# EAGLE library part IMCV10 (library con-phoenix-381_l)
Invertierter Mini-Combicon 3.81mm vertikal 10-polig IMCV 1,5/10-G-3,81 (ohne Gegenstecker)
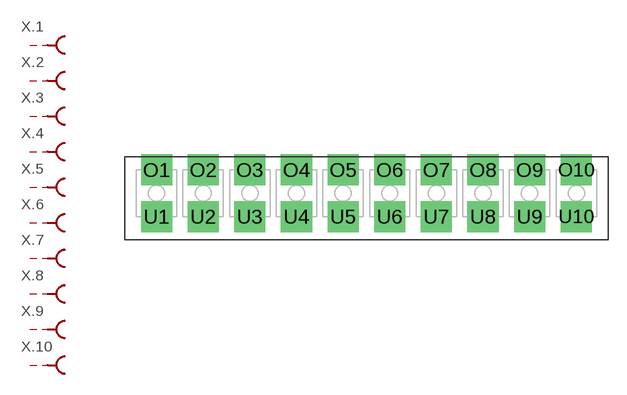
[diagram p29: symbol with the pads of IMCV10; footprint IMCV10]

Designator prefix X; gates .5=MCBU .4=MCBU .3=MCBU .2=MCBU .1=MCBU .6=MCBU .7=MCBU .8=MCBU .9=MCBU .10=MCBU

## IMCV10  [IMCV10]
O1  .1:S  pas
O2  .2:S  pas
O3  .3:S  pas
O4  .4:S  pas
O5  .5:S  pas
O6  .6:S  pas
O7  .7:S  pas
O8  .8:S  pas
O9  .9:S  pas
O10  .10:S  pas
U1  .1:SK  pas
U2  .2:SK  pas
U3  .3:SK  pas
U4  .4:SK  pas
U5  .5:SK  pas
U6  .6:SK  pas
U7  .7:SK  pas
U8  .8:SK  pas
U9  .9:SK  pas
U10  .10:SK  pas

## Footprint IMCV10 (pad centres in mm)
Mini-Combicon 3.81mm vertical 10-polig invertiert (ohne Gegenstecker)
drill 1.3 pad 2.54 square: O1 -17.145,1.905; O2 -13.335,1.905; O3 -9.525,1.905; O4 -5.715,1.905; O5 -1.905,1.905; O6 1.905,1.905; O7 5.715,1.905; O8 9.525,1.905; O9 13.335,1.905; O10 17.145,1.905; U1 -17.145,-1.905; U2 -13.335,-1.905; U3 -9.525,-1.905; U4 -5.715,-1.905; U5 -1.905,-1.905; U6 1.905,-1.905; U7 5.715,-1.905; U8 9.525,-1.905; U9 13.335,-1.905; U10 17.145,-1.905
